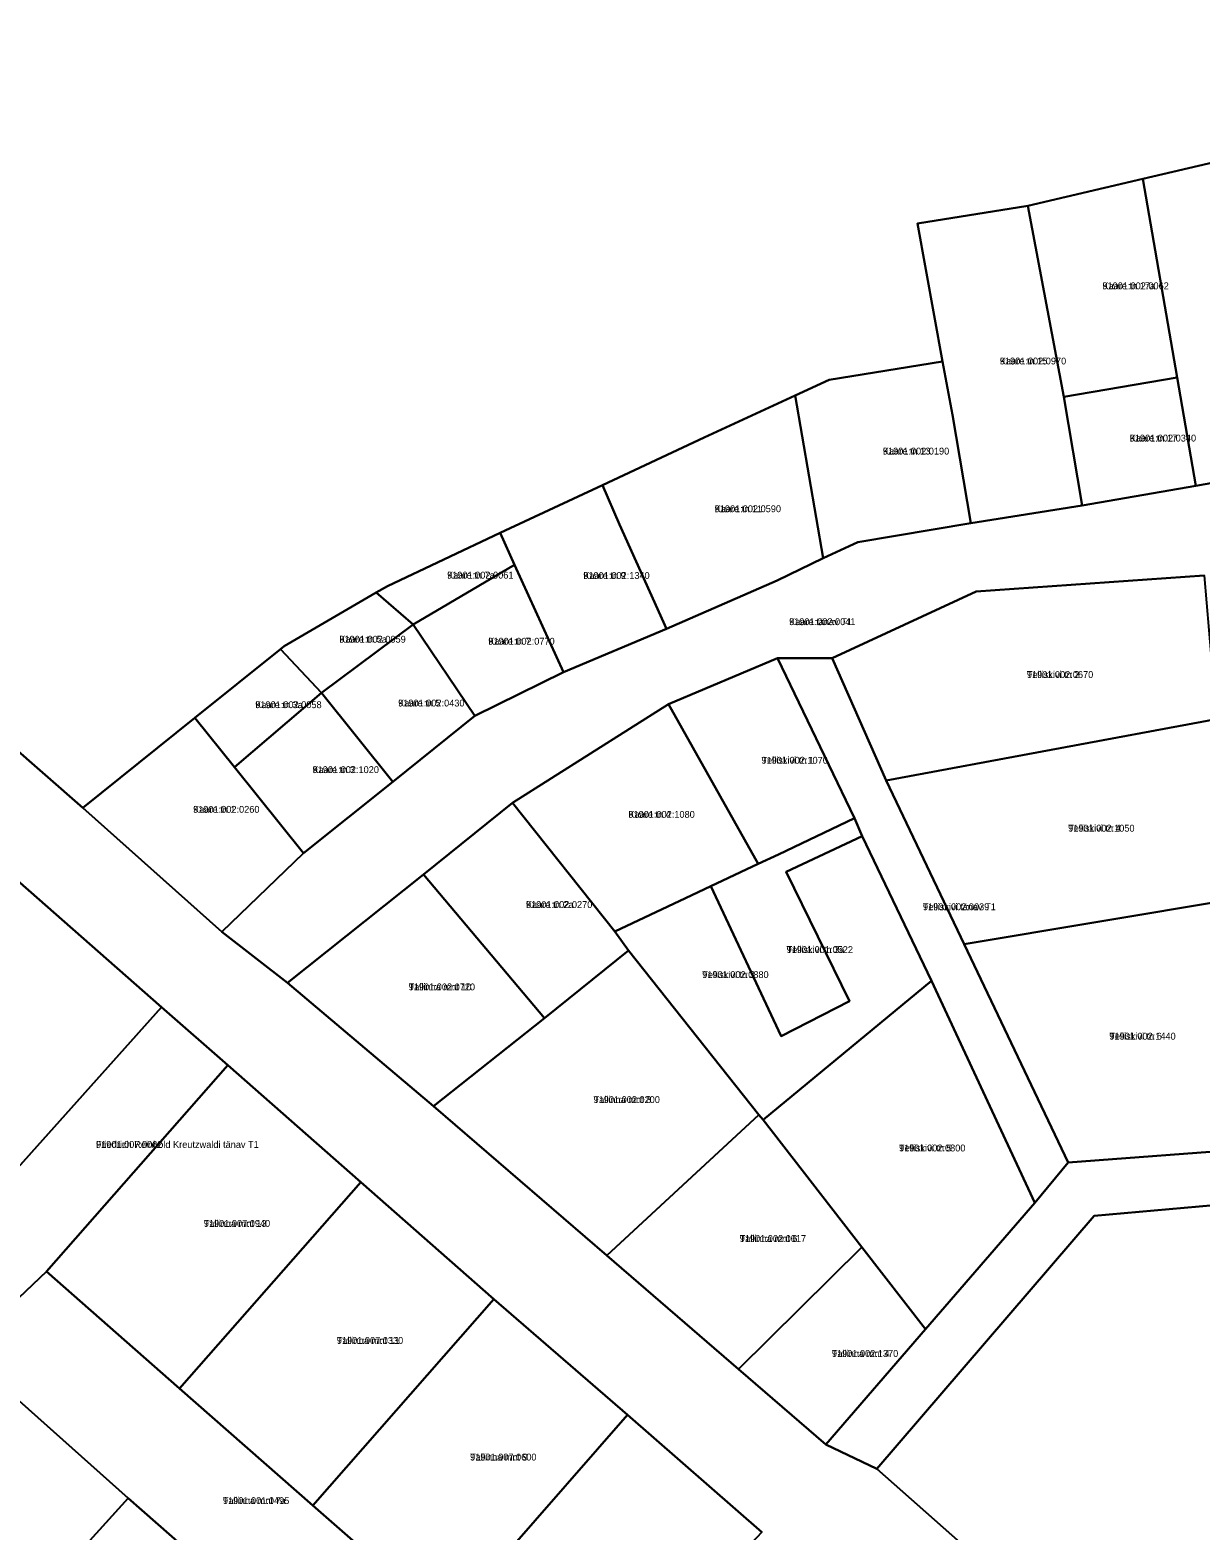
# Model space of a CAD drawing. Extents: x 675810 to 681273, y 6411190 to 6417565.
# Drawn here: x 677289.2 to 677544.8, y 6416055.9 to 6416383.6 of the extents above; entities that cross this region are included whole.
import ezdxf

# ---------------------------------------------------------------- set-up
doc = ezdxf.new("R2010")
doc.units = 0
for name, color, linetype in [('L_AADRESS', 7, 'Continuous'), ('PIIR', 7, 'Continuous'), ('TUNNUS', 7, 'Continuous')]:
    doc.layers.add(name, color=color, linetype=linetype)

msp = doc.modelspace()

# ---------------------------------------------------------------- linework, layer by layer
at = {"layer": 'PIIR'}
for points in [[(677106.6, 6416383.59), (677300.7, 6416213.66), (677331.13, 6416186.57), (677345.42, 6416175.47), (677377.35, 6416148.5), (677415.22, 6416115.85), (677443.97, 6416091.06), (677463.05, 6416074.62), (677474.23, 6416069.26), (677554.29, 6415998.51)], [(677548.9, 6416354.92), (677532.33, 6416351.09), (677507.21, 6416345.16), (677483.1, 6416341.34), (677488.57, 6416311.17), (677463.82, 6416307.19), (677456.35, 6416303.71), (677436.49, 6416294.58), (677414.28, 6416284.18), (677391.89, 6416273.75), (677367.29, 6416262.12), (677364.82, 6416260.72), (677344.69, 6416248.97), (677343.9, 6416248.35), (677325.24, 6416233.34), (677300.7, 6416213.66), (677106.6, 6416383.59)], [(677545.77, 6416264.42), (677495.95, 6416260.96), (677464.48, 6416246.4), (677452.53, 6416246.36), (677428.71, 6416236.35), (677394.64, 6416214.77), (677375.15, 6416199.11), (677345.42, 6416175.47), (677331.13, 6416186.57), (677348.96, 6416203.73), (677368.46, 6416219.38), (677386.39, 6416233.78), (677405.76, 6416243.29), (677428.28, 6416252.78), (677452.44, 6416263.36), (677462.51, 6416268.18), (677470.08, 6416271.71), (677494.73, 6416275.88), (677519.09, 6416279.68), (677543.9, 6416284), (677568.43, 6416288.39)], [(677031.89, 6416017.08), (677061.87, 6416051.99), (677124.93, 6416121.14), (677178.73, 6416183.16), (677227.39, 6416239.26), (677232.52, 6416245.18), (677317.94, 6416170.12), (677283.95, 6416132.21), (677249.95, 6416094.3), (677223.77, 6416062.81), (677219.12, 6416057.2), (677209.12, 6416036.81), (677203.95, 6416024.15), (677201.13, 6415995.28), (677205.18, 6415969.29), (677216.36, 6415942.58), (677231.24, 6415921.83), (677250.14, 6415905.71), (677269.04, 6415889.58), (677212.04, 6415827.9), (677225.12, 6415816.44), (677207.34, 6415789.22), (677214.24, 6415765.69)], [(677449.12, 6416055.4), (677419.76, 6416081.08), (677390.56, 6416106.36), (677361.51, 6416131.89), (677332.43, 6416157.43), (677317.94, 6416170.12), (677232.52, 6416245.18)], [(677283.95, 6416132.21), (677317.94, 6416170.12), (677332.43, 6416157.43), (677292.83, 6416112.36), (677274.52, 6416095.02)]]:
    msp.add_lwpolyline(points, dxfattribs=at)
for points in [[(677568.43, 6416288.39), (677543.9, 6416284), (677539.83, 6416307.7), (677532.33, 6416351.09), (677548.9, 6416354.92), (677550.73, 6416342.26), (677559.92, 6416343.46)], [(677507.21, 6416345.16), (677532.33, 6416351.09), (677539.83, 6416307.7), (677515.07, 6416303.44)], [(677490.72, 6416299.55), (677488.57, 6416311.17), (677483.1, 6416341.34), (677507.21, 6416345.16), (677515.07, 6416303.44), (677519.09, 6416279.68), (677494.73, 6416275.88)], [(677470.08, 6416271.71), (677462.51, 6416268.18), (677456.35, 6416303.71), (677463.82, 6416307.19), (677488.57, 6416311.17), (677490.72, 6416299.55), (677494.73, 6416275.88)], [(677519.09, 6416279.68), (677515.07, 6416303.44), (677539.83, 6416307.7), (677543.9, 6416284)], [(677417.97, 6416275.55), (677414.28, 6416284.18), (677436.49, 6416294.58), (677456.35, 6416303.71), (677462.51, 6416268.18), (677452.44, 6416263.36), (677428.28, 6416252.78)], [(677395.05, 6416266.76), (677391.89, 6416273.75), (677414.28, 6416284.18), (677417.97, 6416275.55), (677428.28, 6416252.78), (677405.76, 6416243.29)], [(677364.82, 6416260.72), (677367.29, 6416262.12), (677391.89, 6416273.75), (677395.05, 6416266.76), (677372.9, 6416253.75)], [(677405.76, 6416243.29), (677386.39, 6416233.78), (677372.9, 6416253.75), (677395.05, 6416266.76)], [(677464.48, 6416246.4), (677495.95, 6416260.96), (677545.77, 6416264.42), (677547.75, 6416240.51), (677548.36, 6416233.03), (677476.27, 6416219.64)], [(677343.9, 6416248.35), (677344.69, 6416248.97), (677364.82, 6416260.72), (677372.9, 6416253.75), (677352.87, 6416238.79)], [(677352.87, 6416238.79), (677372.9, 6416253.75), (677386.39, 6416233.78), (677368.46, 6416219.38)], [(677325.24, 6416233.34), (677343.9, 6416248.35), (677352.87, 6416238.79), (677333.88, 6416222.54)], [(677428.71, 6416236.35), (677452.53, 6416246.36), (677469.33, 6416211.39), (677452.77, 6416203.49), (677448.28, 6416201.4)], [(677452.53, 6416246.36), (677464.48, 6416246.4), (677476.27, 6416219.64), (677493.3, 6416183.91), (677516.04, 6416136.21), (677508.74, 6416127.38), (677486.15, 6416175.87), (677471.05, 6416207.46), (677469.33, 6416211.39)], [(677671, 6416244.77), (677681.85, 6416241.97), (677668.91, 6416222.8), (677656.27, 6416203.57), (677643.64, 6416184.35), (677631, 6416165.12), (677618.37, 6416145.9), (677607.23, 6416129.15), (677603.27, 6416122.92), (677593.8, 6416130.93), (677521.69, 6416124.52), (677474.23, 6416069.26), (677463.05, 6416074.62), (677484.83, 6416099.78), (677508.74, 6416127.38), (677516.04, 6416136.21), (677556.74, 6416139.27), (677581.5, 6416141.12), (677605.73, 6416144.11), (677617.04, 6416162.16), (677637.14, 6416192.47), (677642.75, 6416201.08), (677657.82, 6416224.29), (677666.87, 6416238.47)], [(677333.88, 6416222.54), (677352.87, 6416238.79), (677368.46, 6416219.38), (677348.96, 6416203.73)], [(677394.64, 6416214.77), (677428.71, 6416236.35), (677448.28, 6416201.4), (677437.97, 6416196.57), (677432.4, 6416193.91), (677416.95, 6416186.62)], [(677331.13, 6416186.57), (677300.7, 6416213.66), (677325.24, 6416233.34), (677333.88, 6416222.54), (677348.96, 6416203.73)], [(677476.27, 6416219.64), (677548.36, 6416233.03), (677549.77, 6416216.59), (677551.75, 6416193.61), (677493.3, 6416183.91)], [(677394.64, 6416214.77), (677416.95, 6416186.62), (677419.98, 6416182.51), (677401.61, 6416167.71), (677375.15, 6416199.11)], [(677468.25, 6416171.4), (677453.35, 6416163.8), (677437.97, 6416196.57), (677448.28, 6416201.4), (677452.77, 6416203.49), (677469.33, 6416211.39), (677471.05, 6416207.46), (677454.43, 6416199.68)], [(677416.95, 6416186.62), (677432.4, 6416193.91), (677437.97, 6416196.57), (677453.35, 6416163.8), (677468.25, 6416171.4), (677454.43, 6416199.68), (677471.05, 6416207.46), (677486.15, 6416175.87), (677449.42, 6416145.49), (677448.47, 6416146.6), (677419.98, 6416182.51)], [(677401.61, 6416167.71), (677377.35, 6416148.5), (677345.42, 6416175.47), (677375.15, 6416199.11)], [(677551.75, 6416193.61), (677552.73, 6416185.15), (677556.74, 6416139.27), (677516.04, 6416136.21), (677493.3, 6416183.91)], [(677377.35, 6416148.5), (677401.61, 6416167.71), (677419.98, 6416182.51), (677448.47, 6416146.6), (677415.22, 6416115.85)], [(677484.83, 6416099.78), (677470.93, 6416117.73), (677449.42, 6416145.49), (677486.15, 6416175.87), (677508.74, 6416127.38)], [(677292.83, 6416112.36), (677332.43, 6416157.43), (677361.51, 6416131.89), (677321.89, 6416086.81)], [(677448.47, 6416146.6), (677449.42, 6416145.49), (677470.93, 6416117.73), (677443.97, 6416091.06), (677415.22, 6416115.85)], [(677321.89, 6416086.81), (677361.51, 6416131.89), (677390.56, 6416106.36), (677350.97, 6416061.27)], [(677569.88, 6415984.72), (677567.46, 6415999.42), (677560.49, 6416005.51), (677554.29, 6415998.51), (677474.23, 6416069.26), (677521.69, 6416124.52), (677593.8, 6416130.93), (677603.27, 6416122.92), (677623.31, 6416106.01), (677655.68, 6416078.76), (677573.02, 6415981.95)], [(677484.83, 6416099.78), (677463.05, 6416074.62), (677443.97, 6416091.06), (677470.93, 6416117.73)], [(677292.83, 6416112.36), (677321.89, 6416086.81), (677350.97, 6416061.27), (677380.15, 6416035.75), (677392.98, 6416050.46), (677420.91, 6416025.53), (677426.13, 6416031.12), (677427.25, 6416030.13), (677419.57, 6416021.57), (677397.36, 6416041.78), (677372.67, 6416014.22), (677369.61, 6416010.81), (677349.47, 6416028.77), (677310.65, 6416062.83), (677274.52, 6416095.02)], [(677419.76, 6416081.08), (677392.98, 6416050.46), (677380.15, 6416035.75), (677350.97, 6416061.27), (677390.56, 6416106.36)], [(677274.52, 6416095.02), (677310.65, 6416062.83), (677251.96, 6415998.12), (677280.75, 6415972), (677246.4, 6415934.24), (677232.06, 6415952.28), (677223.66, 6415971.45), (677218.41, 6415993.5), (677219.42, 6416010.9), (677223.33, 6416027.1), (677230.03, 6416042.86), (677235.39, 6416051.02), (677273.35, 6416093.91)], [(677420.91, 6416025.53), (677392.98, 6416050.46), (677419.76, 6416081.08), (677449.12, 6416055.4), (677426.13, 6416031.12)], [(677280.75, 6415972), (677251.96, 6415998.12), (677310.65, 6416062.83), (677349.47, 6416028.77), (677327.9, 6416004.72), (677290.41, 6415962.9), (677285.81, 6415966.98)]]:
    msp.add_lwpolyline(points, close=True, dxfattribs=at)

# ---------------------------------------------------------------- texts
at = {"layer": 'L_AADRESS'}
for s, p in [('Kaare tn 17a', (677523.52, 6416326.95)), ('Kaare tn 15', (677501.1, 6416310.53)), ('Kaare tn 17', (677529.48, 6416293.69)), ('Kaare tn 13', (677475.54, 6416290.85)), ('Kaare tn 11', (677438.79, 6416278.25)), ('Kaare tn 7a', (677380.33, 6416263.75)), ('Kaare tn 9', (677410.09, 6416263.67)), ('Kaare tänav T1', (677455.05, 6416253.58)), ('Kaare tn 5a', (677356.79, 6416249.75)), ('Kaare tn 7', (677389.33, 6416249.31)), ('Telliskivi tn 2', (677507.01, 6416242.03)), ('Kaare tn 3a', (677338.41, 6416235.45)), ('Kaare tn 5', (677369.63, 6416235.81)), ('Telliskivi tn 1', (677449.02, 6416223.31)), ('Kaare tn 3', (677350.93, 6416221.26)), ('Kaare tn 1', (677324.83, 6416212.59)), ('Kaare tn 4', (677419.94, 6416211.49)), ('Telliskivi tn 4', (677516.03, 6416208.47)), ('Kaare tn 2a', (677397.56, 6416191.79)), ('Telliskivi tänav T1', (677484.29, 6416191.3)), ('Telliskivi tn 3a', (677454.51, 6416181.95)), ('Telliskivi tn 3', (677436.08, 6416176.48)), ('Tallinna mnt 10', (677371.93, 6416173.8)), ('Telliskivi tn 6', (677525.02, 6416163.03)), ('Tallinna mnt 8', (677412.32, 6416149.18)), ('Friedrich Reinhold Kreutzwaldi tänav T1', (677303.61, 6416139.38)), ('Telliskivi tn 5', (677479.08, 6416138.61)), ('Tallinna mnt 13', (677327.17, 6416122.13)), ('Tallinna mnt 6', (677444.26, 6416118.83)), ('Tallinna mnt 11', (677356.23, 6416096.57)), ('Tallinna mnt 4', (677464.4, 6416093.72)), ('Tallinna mnt 9', (677385.36, 6416071.09)), ('Tallinna mnt 7a', (677331.34, 6416061.58))]:
    msp.add_text(s, height=1.5, dxfattribs=at).set_placement(p)
at = {"layer": 'TUNNUS'}
for s, p in [('91901:002:0062', (677523.52, 6416326.95)), ('91901:002:0970', (677501.1, 6416310.53)), ('91901:002:0340', (677529.48, 6416293.69)), ('91901:002:0190', (677475.54, 6416290.85)), ('91901:002:0590', (677438.79, 6416278.25)), ('91901:002:0061', (677380.33, 6416263.75)), ('91901:002:1340', (677410.09, 6416263.67)), ('91901:002:0041', (677455.05, 6416253.58)), ('91901:002:0059', (677356.79, 6416249.75)), ('91901:002:0770', (677389.33, 6416249.31)), ('91901:002:0670', (677507.01, 6416242.03)), ('91901:002:0058', (677338.41, 6416235.45)), ('91901:002:0430', (677369.63, 6416235.81)), ('91901:002:1070', (677449.02, 6416223.31)), ('91901:002:1020', (677350.93, 6416221.26)), ('91901:002:0260', (677324.83, 6416212.59)), ('91901:002:1080', (677419.94, 6416211.49)), ('91901:002:1050', (677516.03, 6416208.47)), ('91901:002:0270', (677397.56, 6416191.79)), ('91901:002:0039', (677484.29, 6416191.3)), ('91901:001:0522', (677454.51, 6416181.95)), ('91901:002:0880', (677436.08, 6416176.48)), ('91901:002:0720', (677371.93, 6416173.8)), ('91901:002:1440', (677525.02, 6416163.03)), ('91901:002:0200', (677412.32, 6416149.18)), ('91901:007:0062', (677303.61, 6416139.38)), ('91901:002:0800', (677479.08, 6416138.61)), ('91901:007:0940', (677327.17, 6416122.13)), ('91901:002:0017', (677444.26, 6416118.83)), ('91901:007:0330', (677356.23, 6416096.57)), ('91901:002:1370', (677464.4, 6416093.72)), ('91901:007:0600', (677385.36, 6416071.09)), ('91901:001:0495', (677331.34, 6416061.58))]:
    msp.add_text(s, height=1.5, dxfattribs=at).set_placement(p)

doc.saveas('drawing.dxf')
